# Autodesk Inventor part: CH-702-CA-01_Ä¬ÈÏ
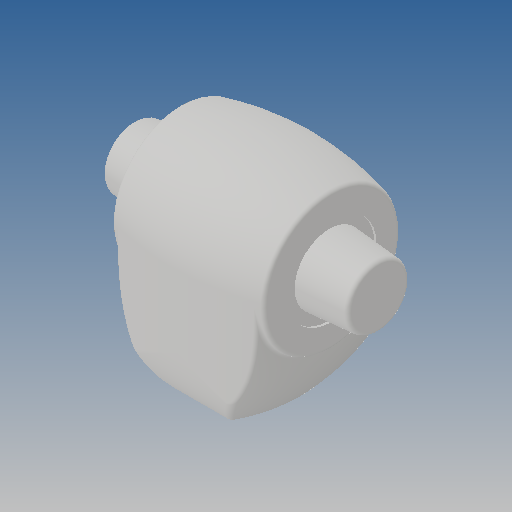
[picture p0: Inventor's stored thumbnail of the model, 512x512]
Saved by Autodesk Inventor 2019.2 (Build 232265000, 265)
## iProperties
Created: 2010-06
Part Number: CH-702-CA-01_Ä¬ÈÏ
Material: Ogólny
Document SubType Name: Modeling
Designer: CADENGINEERING4
Density: 1 g/cm^3
Appearance: Domyślna
Author: CADENGINEERING4
Revision Number: ÈÎºÎ
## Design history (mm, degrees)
feature "NONE"
node "Bryła1"
